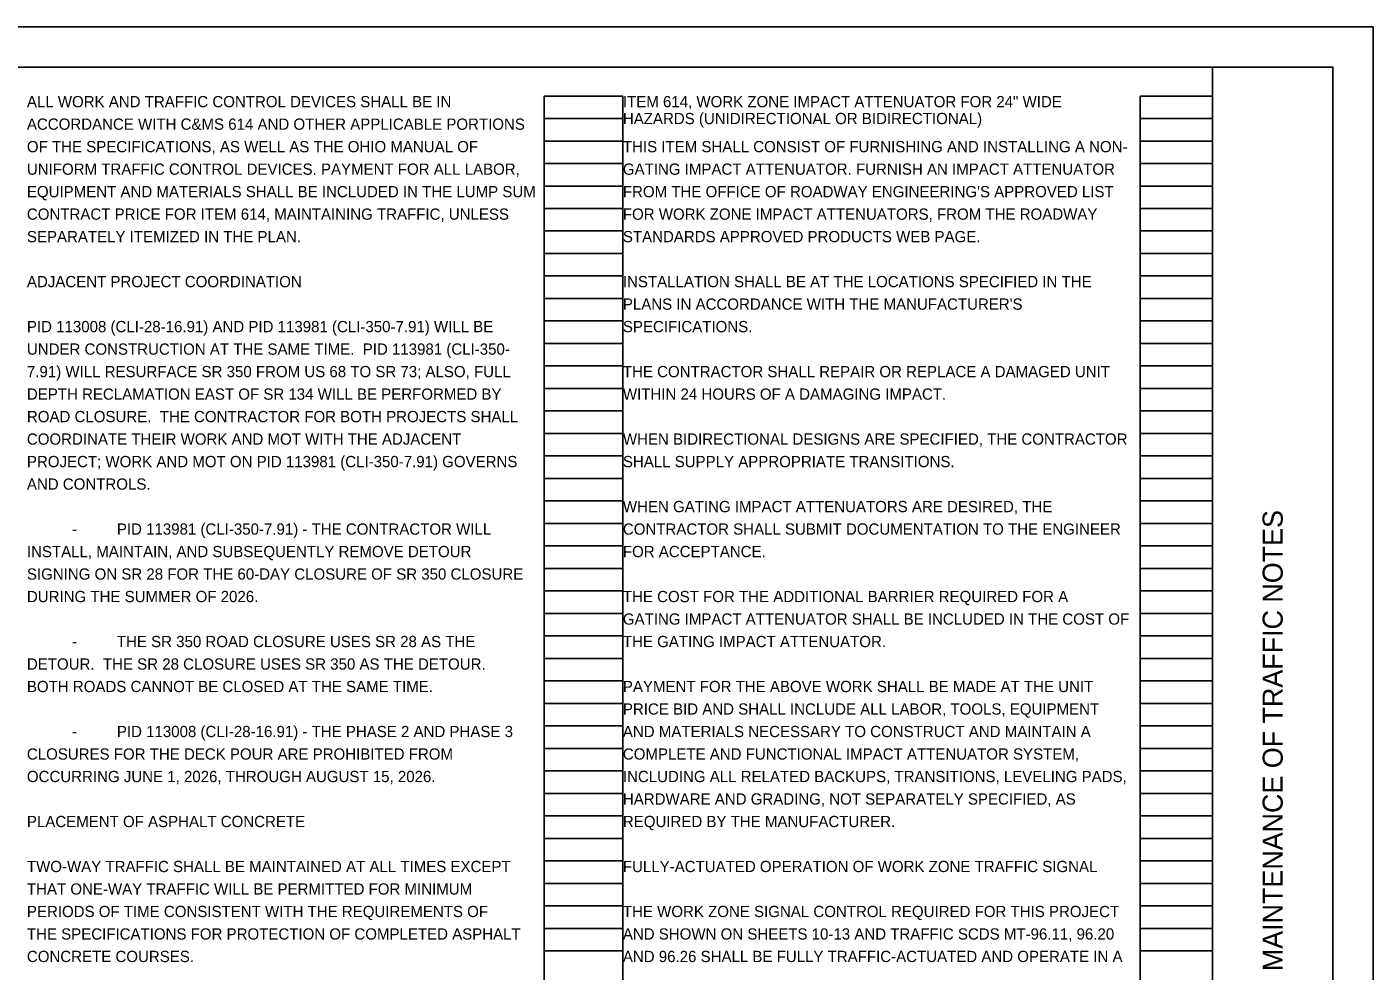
# Model space of a CAD drawing. Extents: x 0 to 34, y 0 to 33.4.
# Drawn here: x 17.24 to 34, y 10.25 to 22 of the extents above; entities that cross this region are included whole.
import ezdxf

# ---------------------------------------------------------------- set-up
doc = ezdxf.new("R2010")
doc.units = 0
for name, color, linetype in [('SH_Border', 7, 'Continuous'), ('SH_Cut_Line', 7, 'Continuous'), ('SH_Data', 7, 'Continuous'), ('TX_X_20', 7, 'Continuous')]:
    doc.layers.add(name, color=color, linetype=linetype)

msp = doc.modelspace()

# ---------------------------------------------------------------- linework, layer by layer
at = {"layer": 'SH_Border'}
msp.add_line((32, 0.5), (32, 21.5), dxfattribs=at)
msp.add_lwpolyline([(1.5, 21.5), (33.5, 21.5), (33.5, 0.5), (1.5, 0.5)], close=True, dxfattribs=at)
at = {"layer": 'SH_Cut_Line'}
msp.add_lwpolyline([(0, 0), (34, 0), (34, 22), (0, 22)], close=True, dxfattribs=at)
at = {"layer": 'SH_Data'}
for p, q in [((23.68, 0.98), (23.68, 21.14)), ((23.68, 21.14), (24.66, 21.14)), ((24.66, 0.98), (24.66, 21.14)), ((31.1, 0.98), (31.1, 21.14)), ((31.1, 21.14), (32, 21.14)), ((32, 0.98), (32, 21.14)), ((23.68, 20.86), (24.66, 20.86)), ((31.1, 20.86), (32, 20.86)), ((23.68, 20.58), (24.66, 20.58)), ((31.1, 20.58), (32, 20.58)), ((23.68, 20.3), (24.66, 20.3)), ((31.1, 20.3), (32, 20.3)), ((23.68, 20.02), (24.66, 20.02)), ((31.1, 20.02), (32, 20.02)), ((23.68, 19.74), (24.66, 19.74)), ((31.1, 19.74), (32, 19.74)), ((23.68, 19.46), (24.66, 19.46)), ((31.1, 19.46), (32, 19.46)), ((23.68, 19.18), (24.66, 19.18)), ((31.1, 19.18), (32, 19.18)), ((23.68, 18.9), (24.66, 18.9)), ((31.1, 18.9), (32, 18.9)), ((23.68, 18.62), (24.66, 18.62)), ((31.1, 18.62), (32, 18.62)), ((23.68, 18.34), (24.66, 18.34)), ((31.1, 18.34), (32, 18.34)), ((23.68, 18.06), (24.66, 18.06)), ((31.1, 18.06), (32, 18.06)), ((23.68, 17.78), (24.66, 17.78)), ((31.1, 17.78), (32, 17.78)), ((23.68, 17.5), (24.66, 17.5)), ((31.1, 17.5), (32, 17.5)), ((23.68, 17.22), (24.66, 17.22)), ((31.1, 17.22), (32, 17.22)), ((23.68, 16.94), (24.66, 16.94)), ((31.1, 16.94), (32, 16.94)), ((23.68, 16.66), (24.66, 16.66)), ((31.1, 16.66), (32, 16.66)), ((23.68, 16.38), (24.66, 16.38)), ((31.1, 16.38), (32, 16.38)), ((23.68, 16.1), (24.66, 16.1)), ((31.1, 16.1), (32, 16.1)), ((23.68, 15.82), (24.66, 15.82)), ((31.1, 15.82), (32, 15.82)), ((23.68, 15.54), (24.66, 15.54)), ((31.1, 15.54), (32, 15.54)), ((23.68, 15.26), (24.66, 15.26)), ((31.1, 15.26), (32, 15.26)), ((23.68, 14.98), (24.66, 14.98)), ((31.1, 14.98), (32, 14.98)), ((23.68, 14.7), (24.66, 14.7)), ((31.1, 14.7), (32, 14.7)), ((23.68, 14.42), (24.66, 14.42)), ((31.1, 14.42), (32, 14.42)), ((23.68, 14.14), (24.66, 14.14)), ((31.1, 14.14), (32, 14.14)), ((23.68, 13.86), (24.66, 13.86)), ((31.1, 13.86), (32, 13.86)), ((23.68, 13.58), (24.66, 13.58)), ((31.1, 13.58), (32, 13.58)), ((23.68, 13.3), (24.66, 13.3)), ((31.1, 13.3), (32, 13.3)), ((23.68, 13.02), (24.66, 13.02)), ((31.1, 13.02), (32, 13.02)), ((23.68, 12.74), (24.66, 12.74)), ((31.1, 12.74), (32, 12.74)), ((23.68, 12.46), (24.66, 12.46)), ((31.1, 12.46), (32, 12.46)), ((23.68, 12.18), (24.66, 12.18)), ((31.1, 12.18), (32, 12.18)), ((23.68, 11.9), (24.66, 11.9)), ((31.1, 11.9), (32, 11.9)), ((23.68, 11.62), (24.66, 11.62)), ((31.1, 11.62), (32, 11.62)), ((23.68, 11.34), (24.66, 11.34)), ((31.1, 11.34), (32, 11.34)), ((23.68, 11.06), (24.66, 11.06)), ((31.1, 11.06), (32, 11.06)), ((23.68, 10.78), (24.66, 10.78)), ((31.1, 10.78), (32, 10.78)), ((23.68, 10.5), (24.66, 10.5)), ((31.1, 10.5), (32, 10.5))]:
    msp.add_line(p, q, dxfattribs=at)

# ---------------------------------------------------------------- texts
msp.add_text('MAINTENANCE OF TRAFFIC NOTES', height=0.25, rotation=90, dxfattribs=at).set_placement((32.875, 10.247))
at = {"layer": 'TX_X_20'}
for s, p in [('ALL WORK AND TRAFFIC CONTROL DEVICES SHALL BE IN ', (17.24, 21)), ('ITEM 614, WORK ZONE IMPACT ATTENUATOR FOR 24" WIDE', (24.66, 21)), ('ACCORDANCE WITH C&MS 614 AND OTHER APPLICABLE PORTIONS ', (17.24, 20.72)), ('HAZARDS (UNIDIRECTIONAL OR BIDIRECTIONAL)', (24.66, 20.79)), ('OF THE SPECIFICATIONS, AS WELL AS THE OHIO MANUAL OF ', (17.24, 20.44)), ('THIS ITEM SHALL CONSIST OF FURNISHING AND INSTALLING A NON-', (24.66, 20.44)), ('UNIFORM TRAFFIC CONTROL DEVICES. PAYMENT FOR ALL LABOR, ', (17.24, 20.16)), ('GATING IMPACT ATTENUATOR. FURNISH AN IMPACT ATTENUATOR ', (24.66, 20.16)), ('EQUIPMENT AND MATERIALS SHALL BE INCLUDED IN THE LUMP SUM ', (17.24, 19.88)), ("FROM THE OFFICE OF ROADWAY ENGINEERING'S APPROVED LIST ", (24.66, 19.88)), ('CONTRACT PRICE FOR ITEM 614, MAINTAINING TRAFFIC, UNLESS ', (17.24, 19.6)), ('FOR WORK ZONE IMPACT ATTENUATORS, FROM THE ROADWAY ', (24.66, 19.6)), ('SEPARATELY ITEMIZED IN THE PLAN.', (17.24, 19.32)), ('STANDARDS APPROVED PRODUCTS WEB PAGE.', (24.66, 19.32)), ('ADJACENT PROJECT COORDINATION', (17.24, 18.76)), ('INSTALLATION SHALL BE AT THE LOCATIONS SPECIFIED IN THE ', (24.66, 18.76)), ("PLANS IN ACCORDANCE WITH THE MANUFACTURER'S ", (24.66, 18.48)), ('PID 113008 (CLI-28-16.91) AND PID 113981 (CLI-350-7.91) WILL BE ', (17.24, 18.2)), ('SPECIFICATIONS.', (24.66, 18.2)), ('UNDER CONSTRUCTION AT THE SAME TIME.  PID 113981 (CLI-350-', (17.24, 17.92)), ('7.91) WILL RESURFACE SR 350 FROM US 68 TO SR 73; ALSO, FULL ', (17.24, 17.64)), ('THE CONTRACTOR SHALL REPAIR OR REPLACE A DAMAGED UNIT ', (24.66, 17.64)), ('DEPTH RECLAMATION EAST OF SR 134 WILL BE PERFORMED BY ', (17.24, 17.36)), ('WITHIN 24 HOURS OF A DAMAGING IMPACT.', (24.66, 17.36)), ('ROAD CLOSURE.  THE CONTRACTOR FOR BOTH PROJECTS SHALL ', (17.24, 17.08)), ('COORDINATE THEIR WORK AND MOT WITH THE ADJACENT ', (17.24, 16.8)), ('WHEN BIDIRECTIONAL DESIGNS ARE SPECIFIED, THE CONTRACTOR ', (24.66, 16.8)), ('PROJECT; WORK AND MOT ON PID 113981 (CLI-350-7.91) GOVERNS ', (17.24, 16.52)), ('SHALL SUPPLY APPROPRIATE TRANSITIONS.', (24.66, 16.52)), ('AND CONTROLS.', (17.24, 16.24)), ('WHEN GATING IMPACT ATTENUATORS ARE DESIRED, THE ', (24.66, 15.96)), ('PID 113981 (CLI-350-7.91) - THE CONTRACTOR WILL ', (18.36, 15.68)), ('CONTRACTOR SHALL SUBMIT DOCUMENTATION TO THE ENGINEER ', (24.66, 15.68)), ('-', (17.8, 15.68)), ('INSTALL, MAINTAIN, AND SUBSEQUENTLY REMOVE DETOUR ', (17.24, 15.4)), ('FOR ACCEPTANCE.', (24.66, 15.4)), ('SIGNING ON SR 28 FOR THE 60-DAY CLOSURE OF SR 350 CLOSURE ', (17.24, 15.12)), ('DURING THE SUMMER OF 2026.  ', (17.24, 14.84)), ('THE COST FOR THE ADDITIONAL BARRIER REQUIRED FOR A', (24.66, 14.84)), ('GATING IMPACT ATTENUATOR SHALL BE INCLUDED IN THE COST OF ', (24.66, 14.56)), ('THE SR 350 ROAD CLOSURE USES SR 28 AS THE ', (18.36, 14.28)), ('THE GATING IMPACT ATTENUATOR.', (24.66, 14.28)), ('-', (17.8, 14.28)), ('DETOUR.  THE SR 28 CLOSURE USES SR 350 AS THE DETOUR.  ', (17.24, 14)), ('BOTH ROADS CANNOT BE CLOSED AT THE SAME TIME.', (17.24, 13.72)), ('PAYMENT FOR THE ABOVE WORK SHALL BE MADE AT THE UNIT', (24.66, 13.72)), ('PRICE BID AND SHALL INCLUDE ALL LABOR, TOOLS, EQUIPMENT', (24.66, 13.44)), ('PID 113008 (CLI-28-16.91) - THE PHASE 2 AND PHASE 3 ', (18.36, 13.16)), ('AND MATERIALS NECESSARY TO CONSTRUCT AND MAINTAIN A', (24.66, 13.16)), ('-', (17.8, 13.16)), ('CLOSURES FOR THE DECK POUR ARE PROHIBITED FROM ', (17.24, 12.88)), ('COMPLETE AND FUNCTIONAL IMPACT ATTENUATOR SYSTEM,', (24.66, 12.88)), ('OCCURRING JUNE 1, 2026, THROUGH AUGUST 15, 2026.', (17.24, 12.6)), ('INCLUDING ALL RELATED BACKUPS, TRANSITIONS, LEVELING PADS, ', (24.66, 12.6)), ('HARDWARE AND GRADING, NOT SEPARATELY SPECIFIED, AS ', (24.66, 12.32)), ('PLACEMENT OF ASPHALT CONCRETE', (17.24, 12.04)), ('REQUIRED BY THE MANUFACTURER.', (24.66, 12.04)), ('TWO-WAY TRAFFIC SHALL BE MAINTAINED AT ALL TIMES EXCEPT', (17.24, 11.48)), ('FULLY-ACTUATED OPERATION OF WORK ZONE TRAFFIC SIGNAL', (24.66, 11.48)), ('THAT ONE-WAY TRAFFIC WILL BE PERMITTED FOR MINIMUM', (17.24, 11.2)), ('PERIODS OF TIME CONSISTENT WITH THE REQUIREMENTS OF', (17.24, 10.92)), ('THE WORK ZONE SIGNAL CONTROL REQUIRED FOR THIS PROJECT ', (24.66, 10.92)), ('THE SPECIFICATIONS FOR PROTECTION OF COMPLETED ASPHALT', (17.24, 10.64)), ('AND SHOWN ON SHEETS 10-13 AND TRAFFIC SCDS MT-96.11, 96.20 ', (24.66, 10.64)), ('CONCRETE COURSES.', (17.24, 10.36)), ('AND 96.26 SHALL BE FULLY TRAFFIC-ACTUATED AND OPERATE IN A ', (24.66, 10.36))]:
    msp.add_text(s, height=0.14, dxfattribs=at).set_placement(p)

doc.saveas('drawing.dxf')
